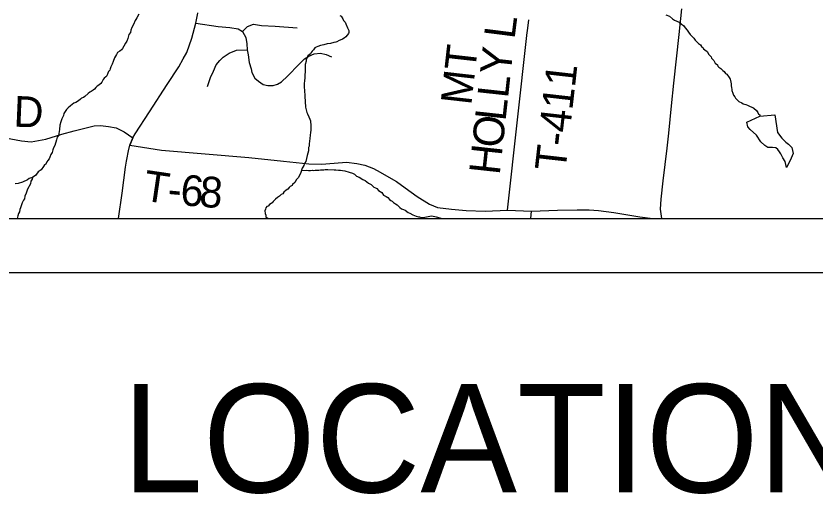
# Model space of a CAD drawing. Extents: x 0 to 34, y 0 to 22.
# Drawn here: x 4.173 to 5.649, y 13.591 to 14.474 of the extents above; entities that cross this region are included whole.
import ezdxf

# ---------------------------------------------------------------- set-up
doc = ezdxf.new("R2010")
doc.units = 0
for name, color, linetype in [('GM_X_Corporation', 7, 'Continuous'), ('GM_X_County_Road', 7, 'Continuous'), ('GM_X_County_Road_Text', 7, 'Continuous'), ('GM_X_Minor_Lake', 7, 'Continuous'), ('GM_X_Minor_River', 7, 'Continuous'), ('GM_X_State_Route', 7, 'Continuous'), ('GM_X_Township_Road', 7, 'Continuous'), ('GM_X_Township_Road_Text', 7, 'Continuous'), ('SH_Data', 7, 'Continuous'), ('SH_Text', 7, 'Continuous')]:
    doc.layers.add(name, color=color, linetype=linetype)

msp = doc.modelspace()

# ---------------------------------------------------------------- linework, layer by layer
at = {"layer": 'GM_X_Corporation'}
msp.add_lwpolyline([(2.9271, 14.1), (8.843, 14.1)], dxfattribs=at)
at = {"layer": 'GM_X_County_Road'}
for p, q in [((4.3883, 14.2487), (4.383, 14.2354)), ((5.1228, 14.1), (5.1244, 14.1135))]:
    msp.add_line(p, q, dxfattribs=at)
for points in [[(4.1437, 14.2504), (4.1833, 14.2432), (4.2011, 14.2415), (4.2278, 14.246), (4.2575, 14.2554), (4.2803, 14.2618), (4.3171, 14.271), (4.3289, 14.2715), (4.3433, 14.2699), (4.3577, 14.2671), (4.3727, 14.2597), (4.3883, 14.2487)], [(4.383, 14.2354), (4.4415, 14.2258), (4.6028, 14.2123), (4.6665, 14.2059), (4.7131, 14.2008), (4.7363, 14.2003), (4.7597, 14.2018), (4.7829, 14.2039), (4.8016, 14.2014), (4.8163, 14.198), (4.8325, 14.1918), (4.845, 14.1852), (4.861, 14.1758), (4.875, 14.168), (4.8909, 14.1561), (4.9134, 14.1402), (4.9359, 14.1265), (4.9504, 14.1201), (4.9766, 14.1169), (5.0037, 14.1142), (5.0384, 14.1132), (5.0798, 14.1149), (5.1244, 14.1135), (5.1721, 14.1149), (5.2082, 14.1156), (5.2306, 14.1156), (5.2475, 14.1146), (5.2762, 14.1107), (5.3239, 14.103), (5.3482, 14.1)]]:
    msp.add_lwpolyline(points, dxfattribs=at)
at = {"layer": 'GM_X_Minor_Lake'}
msp.add_line((4.9243, 14.101), (4.9247, 14.1), dxfattribs=at)
for points in [[(5.5457, 14.2886), (5.5731, 14.2909), (5.5779, 14.2586), (5.5861, 14.2482), (5.5932, 14.2408), (5.5981, 14.2369), (5.6048, 14.2307), (5.6073, 14.22), (5.6033, 14.211), (5.5982, 14.2008), (5.5947, 14.194), (5.5922, 14.2051), (5.5881, 14.212), (5.5845, 14.2193), (5.5815, 14.2231), (5.5785, 14.2274), (5.5748, 14.2305), (5.5687, 14.231), (5.56, 14.2307)], [(5.56, 14.2307), (5.5547, 14.2343), (5.5476, 14.2412), (5.5394, 14.2535), (5.5278, 14.264), (5.5233, 14.269), (5.5216, 14.2774), (5.5457, 14.2886)], [(4.9574, 14.1), (4.9558, 14.1006), (4.949, 14.1022), (4.9395, 14.1039), (4.9243, 14.101)]]:
    msp.add_lwpolyline(points, dxfattribs=at)
at = {"layer": 'GM_X_Minor_River'}
for points in [[(4.3996, 14.4769), (4.396, 14.4701), (4.3937, 14.4675), (4.3929, 14.4652), (4.3898, 14.458), (4.3866, 14.4524), (4.3846, 14.4475), (4.3842, 14.4433), (4.3811, 14.4395), (4.3794, 14.4323), (4.3775, 14.4271), (4.3751, 14.4237), (4.372, 14.418), (4.3696, 14.4139), (4.3673, 14.4113), (4.3646, 14.4087), (4.3604, 14.4064), (4.358, 14.4027), (4.3565, 14.3993), (4.3545, 14.3963), (4.3521, 14.3899), (4.3505, 14.3846), (4.3481, 14.3797), (4.3466, 14.3763), (4.3461, 14.3736), (4.3438, 14.3714), (4.3423, 14.3683), (4.3403, 14.3634), (4.3387, 14.3612), (4.3356, 14.359), (4.3337, 14.3563), (4.3313, 14.3518), (4.3294, 14.3492), (4.3259, 14.3462), (4.3228, 14.344), (4.3201, 14.3417), (4.3178, 14.3384), (4.3155, 14.3365), (4.3116, 14.3343), (4.309, 14.3328), (4.3059, 14.3306), (4.3001, 14.325), (4.2974, 14.3231), (4.2939, 14.3217), (4.2916, 14.3202), (4.2882, 14.3172), (4.2835, 14.3139), (4.2797, 14.3128), (4.2766, 14.3102), (4.2732, 14.3076), (4.2693, 14.3042), (4.2658, 14.3009), (4.2635, 14.2975), (4.2612, 14.2937), (4.2603, 14.2899), (4.2576, 14.2835), (4.2556, 14.2782), (4.254, 14.2722), (4.2531, 14.2642), (4.2522, 14.2604), (4.251, 14.2532), (4.249, 14.2498), (4.2474, 14.2453), (4.2446, 14.2347), (4.2422, 14.2305), (4.241, 14.2267), (4.2394, 14.2214), (4.2374, 14.2177), (4.2355, 14.2128), (4.2343, 14.2097), (4.2316, 14.2071), (4.2296, 14.2041), (4.228, 14.2003), (4.2257, 14.1989)], [(4.7706, 14.4749), (4.7732, 14.4737), (4.7758, 14.4687), (4.7773, 14.4657), (4.7803, 14.4626), (4.7817, 14.4591), (4.7847, 14.4518), (4.7857, 14.4492), (4.7872, 14.4469), (4.7868, 14.4434), (4.7864, 14.4412), (4.7837, 14.4382), (4.7817, 14.4352), (4.7786, 14.4329), (4.7752, 14.4311), (4.7713, 14.4289), (4.769, 14.4282), (4.7652, 14.4259), (4.7629, 14.4252), (4.7595, 14.4249), (4.753, 14.4231), (4.7473, 14.4225), (4.7408, 14.4203), (4.7347, 14.4193), (4.7297, 14.4171), (4.7266, 14.416), (4.7243, 14.4149), (4.722, 14.4115), (4.7193, 14.4089), (4.7177, 14.4066), (4.7162, 14.404), (4.7139, 14.4021), (4.7112, 14.3999), (4.71, 14.3969), (4.708, 14.3939), (4.708, 14.3901), (4.7067, 14.384), (4.7063, 14.381), (4.7066, 14.3775), (4.7065, 14.3718), (4.706, 14.3638), (4.7056, 14.3604), (4.7051, 14.3536), (4.7046, 14.3494), (4.7046, 14.3468), (4.7049, 14.3422), (4.7052, 14.3361), (4.7055, 14.3331), (4.7058, 14.3292), (4.7058, 14.327), (4.7061, 14.3232), (4.7064, 14.3178), (4.7063, 14.3129), (4.707, 14.3087), (4.7073, 14.3053), (4.7084, 14.3003), (4.7094, 14.2957), (4.7109, 14.293), (4.7135, 14.2877), (4.7153, 14.2831), (4.7164, 14.28), (4.7163, 14.2773), (4.7167, 14.2739), (4.717, 14.2697), (4.7168, 14.2629), (4.7164, 14.2587), (4.7159, 14.2534), (4.7151, 14.2477), (4.7141, 14.2378), (4.7137, 14.2336)], [(5.3721, 14.4761), (5.3788, 14.4734), (5.3841, 14.4687), (5.3882, 14.466), (5.3924, 14.4644), (5.3969, 14.4624), (5.401, 14.4585), (5.4048, 14.4562), (5.4078, 14.4519), (5.4115, 14.4473), (5.4137, 14.4438), (5.4171, 14.4396), (5.4204, 14.4361), (5.4234, 14.4326), (5.4264, 14.4292), (5.4324, 14.423), (5.4361, 14.4203), (5.438, 14.4172), (5.441, 14.4152), (5.4417, 14.4129), (5.444, 14.4114), (5.4481, 14.4079), (5.4514, 14.4025), (5.4555, 14.3986), (5.4562, 14.3959), (5.4607, 14.3917), (5.4633, 14.3867), (5.4671, 14.3836), (5.4678, 14.3813), (5.47, 14.3793), (5.4734, 14.377), (5.4771, 14.3731), (5.4798, 14.3712), (5.4824, 14.3677), (5.4846, 14.3665), (5.4887, 14.36), (5.4909, 14.3569), (5.4913, 14.3546), (5.492, 14.3516), (5.4923, 14.3485), (5.4923, 14.3447), (5.493, 14.3417), (5.4937, 14.3382), (5.494, 14.3359), (5.4954, 14.331), (5.4969, 14.3275), (5.4991, 14.3244), (5.5006, 14.3221), (5.5047, 14.3179), (5.507, 14.3159), (5.5123, 14.3132), (5.5149, 14.3116), (5.5172, 14.3108), (5.5194, 14.3104), (5.5228, 14.3092), (5.5251, 14.308), (5.5277, 14.3068), (5.5323, 14.3048), (5.5345, 14.3033), (5.5394, 14.299), (5.5416, 14.2952), (5.5431, 14.2925), (5.5453, 14.2909), (5.5457, 14.2886)], [(4.7137, 14.2336), (4.7129, 14.231), (4.7128, 14.2287), (4.7124, 14.2249), (4.7116, 14.2204), (4.71, 14.2158), (4.7075, 14.2052), (4.7059, 14.2026), (4.7048, 14.1999), (4.7043, 14.1973), (4.702, 14.1947), (4.7012, 14.1924), (4.6984, 14.1848), (4.6972, 14.1818), (4.6933, 14.1747), (4.6906, 14.172), (4.6871, 14.166), (4.6832, 14.1627), (4.6824, 14.1604), (4.679, 14.1589), (4.677, 14.1567), (4.6743, 14.1537), (4.6713, 14.1519), (4.6674, 14.1481), (4.6651, 14.1455), (4.6624, 14.144), (4.6589, 14.141), (4.6554, 14.1388), (4.652, 14.1355), (4.6497, 14.1336), (4.6477, 14.131), (4.6458, 14.1287), (4.6435, 14.1272), (4.6404, 14.1254), (4.6381, 14.1228), (4.6358, 14.1217), (4.6338, 14.1194), (4.633, 14.1168), (4.6322, 14.1137), (4.6325, 14.1092), (4.6336, 14.1057), (4.6339, 14.1031), (4.6381, 14.1)], [(4.2257, 14.1989), (4.2234, 14.1959), (4.2191, 14.1899), (4.2137, 14.1858), (4.2091, 14.1794), (4.206, 14.1775), (4.2033, 14.1753), (4.2025, 14.1723), (4.2001, 14.1689), (4.1993, 14.1636), (4.1942, 14.1538), (4.1914, 14.1466), (4.1894, 14.1409), (4.1886, 14.136), (4.1866, 14.1334), (4.1842, 14.1285), (4.1811, 14.1194), (4.1802, 14.1164), (4.179, 14.1122), (4.1775, 14.1092), (4.1762, 14.1046), (4.1752, 14.1)], [(4.6998, 14.1885), (4.7088, 14.1888), (4.7129, 14.1884), (4.716, 14.1883), (4.7198, 14.1887), (4.7221, 14.1886), (4.7251, 14.1889), (4.7285, 14.1889), (4.7316, 14.1892), (4.735, 14.1895), (4.7373, 14.1899), (4.7407, 14.1898), (4.7434, 14.1901), (4.7483, 14.1901), (4.7597, 14.1898), (4.7631, 14.1894), (4.7681, 14.1889), (4.7719, 14.1889), (4.7753, 14.1884), (4.7794, 14.1876), (4.7874, 14.1856), (4.7938, 14.1832), (4.7976, 14.1816), (4.8013, 14.1781), (4.8062, 14.1761), (4.8126, 14.1718), (4.8172, 14.1698), (4.8235, 14.1648), (4.8281, 14.1624), (4.8333, 14.1577), (4.8363, 14.1566), (4.8386, 14.155), (4.8416, 14.1515), (4.845, 14.1496), (4.848, 14.1476), (4.8513, 14.143), (4.8558, 14.1406), (4.8588, 14.1383), (4.8618, 14.1348), (4.8648, 14.1332), (4.8671, 14.1317), (4.8697, 14.129), (4.8731, 14.127), (4.8765, 14.125), (4.8813, 14.12), (4.8843, 14.1177), (4.8877, 14.1165), (4.8911, 14.1149), (4.8964, 14.111), (4.8998, 14.1098), (4.9054, 14.1063), (4.9115, 14.1043), (4.9153, 14.1031), (4.9175, 14.1026), (4.9206, 14.1018), (4.9228, 14.1014), (4.9243, 14.101)], [(4.2032, 14.1752), (4.1972, 14.1739), (4.1941, 14.1713), (4.1849, 14.1669), (4.1769, 14.1644), (4.1712, 14.1637)]]:
    msp.add_lwpolyline(points, dxfattribs=at)
at = {"layer": 'GM_X_State_Route'}
msp.add_line((4.383, 14.2354), (4.3883, 14.2487), dxfattribs=at)
for points in [[(5.3644, 14.1), (5.362, 14.1168), (5.3634, 14.1352), (5.3674, 14.1694), (5.3743, 14.2295), (5.3777, 14.2573), (5.3825, 14.3079), (5.3869, 14.3499), (5.3969, 14.4397), (5.4015, 14.487)], [(4.3883, 14.2487), (4.393, 14.2561), (4.419, 14.2968), (4.4517, 14.3473), (4.4733, 14.3799), (4.4815, 14.3947), (4.4879, 14.4065), (4.4972, 14.4325), (4.5045, 14.4606), (4.5083, 14.4788), (4.5085, 14.4798)], [(4.3768, 14.2057), (4.3773, 14.2087), (4.3803, 14.225), (4.383, 14.2354)], [(4.3621, 14.1), (4.3687, 14.1464), (4.3752, 14.1948), (4.3768, 14.2057)]]:
    msp.add_lwpolyline(points, dxfattribs=at)
at = {"layer": 'GM_X_Township_Road'}
msp.add_line((5.1165, 14.4462), (5.1191, 14.4666), dxfattribs=at)
for points in [[(4.5045, 14.4606), (4.5458, 14.4544), (4.5676, 14.4524), (4.583, 14.4497)], [(4.5909, 14.4452), (4.6001, 14.4543), (4.6111, 14.4584), (4.6257, 14.4562), (4.6514, 14.4548), (4.6915, 14.4518)], [(4.583, 14.4497), (4.5909, 14.4452), (4.5972, 14.434), (4.599, 14.4223), (4.5997, 14.4115), (4.601, 14.4019), (4.603, 14.3878), (4.6068, 14.3761), (4.6082, 14.3694), (4.6137, 14.3591), (4.6205, 14.3533), (4.6291, 14.3474), (4.6377, 14.3454), (4.6472, 14.3456), (4.6556, 14.3477), (4.6625, 14.3522), (4.6737, 14.3626), (4.6953, 14.3846), (4.7053, 14.3947), (4.713, 14.3995), (4.7229, 14.4039), (4.7347, 14.405), (4.7452, 14.4028), (4.755, 14.3985)], [(5.0798, 14.1149), (5.116, 14.4431), (5.1165, 14.4462)], [(4.5263, 14.3436), (4.532, 14.3602), (4.5371, 14.3716), (4.5425, 14.3835), (4.5488, 14.3918), (4.555, 14.3978), (4.5662, 14.4053), (4.5799, 14.4104), (4.5997, 14.4115)]]:
    msp.add_lwpolyline(points, dxfattribs=at)
at = {"layer": 'SH_Data'}
for p, q in [((2.1, 14.1), (8.9, 14.1)), ((2, 14), (9, 14))]:
    msp.add_line(p, q, dxfattribs=at)

# ---------------------------------------------------------------- texts
at = {"layer": 'GM_X_County_Road_Text'}
msp.add_text('D', height=0.0568, rotation=357.573, dxfattribs=at).set_placement((4.1676, 14.2695))
at = {"layer": 'GM_X_Township_Road_Text'}
for s, height, rotation, p in [('L', 0.0568, 82.7809, (5.0927, 14.4297)), ('MT', 0.05682, 83.5584, (5.0129, 14.3077)), ('Y', 0.0568, 83.7073, (5.0853, 14.3628)), ('T-411', 0.05682, 83.5362, (5.1866, 14.1855)), ('L', 0.0568, 83.7909, (5.0807, 14.3206)), ('L', 0.0568, 83.7911, (5.0761, 14.2783)), ('O', 0.0568, 83.7877, (5.0707, 14.2286)), ('H', 0.0568, 83.7913, (5.0653, 14.1789)), ('T', 0.0568, 351.6172, (4.4054, 14.1332)), ('6', 0.0568, 355.4977, (4.4748, 14.1245)), ('8', 0.0568, 355.6738, (4.5099, 14.1217)), ('-', 0.0568, 355.0549, (4.4511, 14.1265))]:
    msp.add_text(s, height=height, rotation=rotation, dxfattribs=at).set_placement(p)
at = {"layer": 'SH_Text'}
msp.add_text('LOCATION MAP', height=0.2, dxfattribs=at).set_placement((4.3691, 13.5938))

doc.saveas('drawing.dxf')
